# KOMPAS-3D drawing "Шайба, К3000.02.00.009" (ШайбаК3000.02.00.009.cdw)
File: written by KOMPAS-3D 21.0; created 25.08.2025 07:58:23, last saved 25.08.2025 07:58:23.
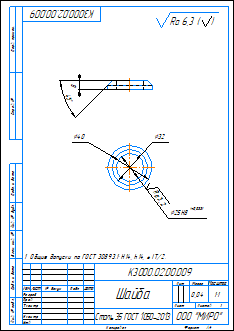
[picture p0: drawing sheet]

Sheet 1: A4, portrait

Document properties: Автор: admin; Полное имя файла: C:\Users\ShavarinML\Desktop\Стапель\2D\ШайбаК3000.02.00.009.cdw; Знак неуказанной шероховатости: 4; Параметр неуказанной шероховатости: Ra 6,3; Масса: 0.0406

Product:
- Part/product: Шайба  | designation К3000.02.00.009
    Материал: Сталь 35 ГОСТ 1050-2013 (density 7826 kg/m3)
    Масса: 0.0406

Title block, sheet 1: Наименование: Шайба; designation: К3000.02.00.009; Материал: Сталь 35 ГОСТ 1050-2013; Масса: 0,04; Количество листов документа: 1; organisation: ООО "МИРО"; Форматы листов документа: A4

Views: Спереди 1, Спереди, Проекционный вид 2
Referenced files in C:\Users\ShavarinML\Desktop\Стапель\Задняя бабака\Из трубы\: Шайба 2.m3d
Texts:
  Ra 3,2
  Ra 6,3
  Ra 6,3 ( )
  К3000.02.00.009 Шайба
Dimensions and other numbers on the sheet: 8; 25; 32; 40; 1:1; 1; 0,04

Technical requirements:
  Общие допуски по ГОСТ 30893.1: H14, h14,   IT/2.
